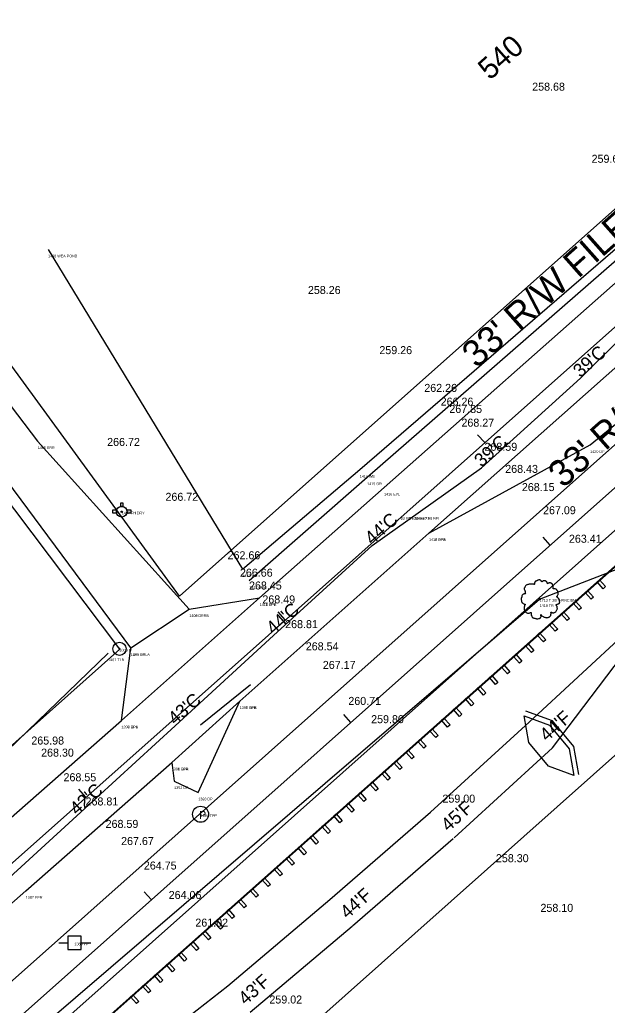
# Model space of a CAD drawing. Extents: x 49683 to 58852, y 49525 to 54803.
# Drawn here: x 54911.8 to 55132.1, y 52731.5 to 53100.7 of the extents above; entities that cross this region are included whole.
import ezdxf

# ---------------------------------------------------------------- set-up
doc = ezdxf.new("R2010")
doc.units = 0
for name, color, linetype in [('Level 1', 7, 'Continuous'), ('Level 10', 7, 'Continuous'), ('Level 11', 7, 'Continuous'), ('Level 12', 7, 'Continuous'), ('Level 13', 7, 'Continuous'), ('Level 18', 7, 'Continuous'), ('Level 19', 7, 'Continuous'), ('Level 20', 7, 'Continuous'), ('Level 21', 7, 'Continuous'), ('Level 25', 7, 'Continuous'), ('Level 27', 7, 'Continuous'), ('Level 3', 7, 'Continuous'), ('Level 32', 7, 'Continuous'), ('Level 33', 7, 'Continuous'), ('Level 34', 7, 'Continuous'), ('Level 48', 7, 'Continuous'), ('Level 51', 7, 'Continuous'), ('Level 53', 7, 'Continuous'), ('Level 57', 7, 'Continuous'), ('Level 58', 7, 'Continuous'), ('Level 59', 7, 'Continuous'), ('Level 60', 7, 'Continuous'), ('Level 61', 7, 'Continuous'), ('Level 62', 7, 'Continuous'), ('Level 7', 7, 'Continuous'), ('Level 8', 7, 'Continuous'), ('Level 9', 7, 'Continuous')]:
    doc.layers.add(name, color=color, linetype=linetype)

# ---------------------------------------------------------------- blocks, each defined once
blk = doc.blocks.new('PP')
at = {"layer": 'Level 9'}
for p, q in [((2.53, 2.45), (-2.47, 2.45)), ((-2.47, 2.45), (-2.47, -2.55)), ((2.53, -2.55), (2.53, 2.45)), ((-5.91, -0.11), (-2.44, -0.11)), ((-2.47, -2.55), (2.53, -2.55)), ((2.45, -0.11), (6.09, -0.11))]:
    blk.add_line(p, q, dxfattribs=at)
blk = doc.blocks.new('TPP')
at = {"layer": 'Level 9'}
blk.add_circle((0, 0), 3, dxfattribs=at)
blk.add_text('P', height=3, dxfattribs=at).set_placement((-0.59, -1.73))
blk = doc.blocks.new('FH')
at = {"layer": 'Level 9'}
for p, q in [((-1.92, 0.57), (-3.47, 0.57)), ((-3.47, 0.57), (-3.47, -0.43)), ((-0.46, 3.22), (-0.46, 1.95)), ((0.54, 3.22), (-0.46, 3.22)), ((0.54, 1.92), (0.54, 3.22)), ((3.53, 0.57), (1.92, 0.57)), ((3.53, -0.43), (3.53, 0.57)), ((-3.47, -0.43), (-1.95, -0.43)), ((1.95, -0.43), (3.53, -0.43))]:
    blk.add_line(p, q, dxfattribs=at)
for radius in [2, 0.25]:
    blk.add_circle((0, 0), radius, dxfattribs=at)
for start, end in [(163.3387, 192.315), (74.2455, 103.2128), (347.685, 16.6613)]:
    blk.add_arc((0, 0), 2, start, end, dxfattribs=at)
blk = doc.blocks.new('T1')
at = {"layer": 'Level 11'}
for centre, radius in [((0, 0), 0.25), ((-0.01, -0.02), 0.0001)]:
    blk.add_circle(centre, radius, dxfattribs=at)
for points in [[(0.13, 7.17), (-0.17, 7.19), (-0.49, 7.09), (-0.74, 6.99), (-0.97, 6.92), (-1.19, 6.82), (-1.49, 6.64), (-1.72, 6.44), (-1.84, 6.19), (-1.89, 5.97), (-1.94, 5.69), (-1.94, 5.52), (-2.07, 5.49), (-2.22, 5.52), (-2.47, 5.59), (-2.72, 5.59), (-2.97, 5.59), (-3.32, 5.57), (-3.67, 5.57), (-3.94, 5.52), (-4.27, 5.47), (-4.64, 5.34), (-4.99, 5.22), (-5.29, 4.97), (-5.54, 4.49), (-5.67, 4.14), (-5.82, 3.89), (-5.67, 3.44), (-5.49, 3.09), (-5.47, 2.89), (-5.39, 2.47), (-5.29, 2.24), (-5.17, 2.04), (-5.24, 2.02), (-5.62, 1.97), (-5.92, 1.87), (-6.34, 1.64), (-6.57, 1.42), (-6.67, 1.09), (-6.69, 0.75), (-6.79, 0.55), (-6.87, 0.27), (-6.89, 0.2), (-6.94, -0.13), (-6.84, -0.58), (-6.82, -0.93), (-6.69, -1.15), (-6.54, -1.33), (-6.37, -1.58), (-5.97, -1.8), (-5.64, -1.9), (-5.44, -1.93), (-5.62, -2.43), (-5.67, -2.78), (-5.79, -3.18), (-5.79, -3.25), (-5.84, -3.73), (-5.69, -4.05), (-5.62, -4.43), (-5.44, -4.65), (-5.17, -4.95), (-4.84, -5.18), (-4.34, -5.3), (-3.94, -5.28), (-3.37, -5.1), (-3.12, -5.03), (-3.14, -5.2), (-3.12, -5.58), (-3.12, -6), (-2.97, -6.33), (-2.87, -6.6), (-2.72, -6.85), (-2.39, -7.08), (-1.99, -7.15), (-1.57, -7.3), (-1.12, -7.38), (-0.62, -7.4), (-0.02, -7.25), (0.26, -7.13), (0.36, -6.95), (0.56, -6.58), (0.51, -6.35), (0.53, -5.75), (0.63, -5.93), (0.81, -6.28), (1.31, -6.58), (1.71, -6.75), (2.18, -6.9), (2.48, -6.98), (2.96, -6.9), (3.33, -6.83), (3.71, -6.7), (4.01, -6.43), (4.18, -6.15), (4.23, -5.88), (4.31, -5.5), (4.36, -5.33)], [(4.36, -5.33), (4.28, -5.15), (4.23, -4.9), (4.31, -4.93), (4.48, -4.98), (4.75, -5.1), (4.98, -5.18), (5.3, -5.15), (5.58, -5.05), (6.03, -4.78), (6.3, -4.3), (6.58, -3.9), (6.65, -3.58), (6.6, -3.35), (6.58, -2.85), (6.38, -2.6), (6.33, -2.48), (6.23, -2.08), (6.3, -2.03), (6.58, -1.98), (6.95, -1.85), (7.23, -1.73), (7.45, -1.55), (7.53, -1.33), (7.5, -0.93), (7.55, -0.53), (7.48, -0.38), (7.38, -0.23), (7.3, -0.03), (7.15, 0.12), (7.05, 0.27), (6.95, 0.37), (6.83, 0.52), (6.65, 0.65), (6.5, 0.7), (6.45, 0.85), (6.6, 1.04), (6.65, 1.14), (6.68, 1.37), (6.9, 1.72), (6.95, 2.12), (6.9, 2.54), (6.85, 2.82), (6.7, 3.09), (6.5, 3.34), (6.38, 3.52), (6.2, 3.64), (5.88, 3.77), (5.63, 3.82), (5.28, 3.82), (5.08, 3.87), (5.1, 3.92), (5.1, 4.07), (5.1, 4.34), (5.03, 4.79), (4.88, 5.29), (4.88, 5.32), (4.78, 5.57), (4.56, 5.77), (4.38, 5.87), (4.18, 5.99), (3.93, 6.02), (3.63, 6.02), (3.36, 5.97), (3.16, 5.87), (2.98, 5.74), (2.91, 5.89), (2.81, 6.19), (2.76, 6.34), (2.61, 6.52), (2.38, 6.72), (1.93, 6.84), (1.31, 6.77), (1.01, 6.57), (0.86, 6.39), (0.81, 6.52), (0.61, 6.72), (0.51, 6.89), (0.33, 7.02), (0.18, 7.12), (0.08, 7.17)]]:
    blk.add_spline(points, degree=3, dxfattribs=at)
blk = doc.blocks.new('IP')
at = {"layer": 'Level 12'}
for radius in [2.5, 0.25]:
    blk.add_circle((0, 0), radius, dxfattribs=at)

msp = doc.modelspace()

# ---------------------------------------------------------------- linework, layer by layer
at = {"layer": 'Level 1'}
for p, q in [((52544.81, 50683.3), (55534.58, 53340.86)), ((55086.14, 52942.25), (55083.48, 52945.23)), ((55011.4, 52875.81), (55008.74, 52878.8)), ((54936.65, 52809.37), (54934, 52812.36))]:
    msp.add_line(p, q, dxfattribs=at)
at = {"layer": 'Level 10'}
for p, q in [((55039.31, 52932.12), (55223.63, 53091.32)), ((54922.47, 53014.66), (54995.29, 52894.87)), ((54995.29, 52894.87), (55039.31, 52932.12))]:
    msp.add_line(p, q, dxfattribs=at)
at = {"layer": 'Level 11'}
for p, q in [((55106.73, 52883.65), (55187.95, 52915.03)), ((54913.43, 52717.81), (55106.73, 52883.65)), ((54711.21, 52637.72), (54944.99, 52863.38))]:
    msp.add_line(p, q, dxfattribs=at)
at = {"layer": 'Level 12'}
for p, q in [((54949.37, 52864.83), (54608.23, 53316.46)), ((54971.79, 52884.76), (54817.75, 53095.57))]:
    msp.add_line(p, q, dxfattribs=at)
at = {"layer": 'Level 13'}
for p, q in [((54971.79, 52884.76), (55235.68, 53119.33)), ((55279.53, 53070), (53969.03, 51905.11)), ((54949.37, 52864.83), (53925.18, 51954.44))]:
    msp.add_line(p, q, dxfattribs=at)
at = {"layer": 'Level 18'}
for p, q in [((55122.01, 52966.38), (55157.54, 53001.67)), ((55084.95, 52932.81), (55122.01, 52966.38)), ((55043.92, 52903.71), (55084.95, 52932.81)), ((55006.97, 52870.02), (55043.92, 52903.71)), ((55102.79, 52837.48), (55139.49, 52871.45)), ((54970.15, 52836.18), (55006.97, 52870.02)), ((55111.62, 52827.94), (55142.56, 52868.88)), ((55065.87, 52803.76), (55102.79, 52837.48)), ((54933.3, 52802.37), (54970.15, 52836.18)), ((55074.64, 52794.16), (55111.56, 52827.88)), ((54896.29, 52768.76), (54933.3, 52802.37)), ((55028.03, 52771.07), (55065.87, 52803.76)), ((55036.53, 52761.23), (55074.37, 52793.92)), ((54989.87, 52738.74), (55028.03, 52771.07)), ((54998.27, 52728.82), (55036.43, 52761.15)), ((54950.34, 52707.95), (54989.87, 52738.74))]:
    msp.add_line(p, q, dxfattribs=at)
at = {"layer": 'Level 19'}
for p, q in [((54181.77, 52078.16), (56150.85, 53828.45)), ((55110.69, 52903.86), (55108.03, 52906.85)), ((55035.94, 52837.42), (55033.29, 52840.41)), ((54961.2, 52770.99), (54958.55, 52773.98))]:
    msp.add_line(p, q, dxfattribs=at)
at = {"layer": 'Level 20'}
for p, q in [((54173.8, 52087.13), (55269.45, 53061.04)), ((54189.74, 52069.19), (55278.86, 53037.3))]:
    msp.add_line(p, q, dxfattribs=at)
at = {"layer": 'Level 27'}
for p, q in [((54196.38, 52061.72), (55282.79, 53027.4)), ((54196.55, 52061.53), (55282.95, 53027.22)), ((55128.29, 52890.07), (55129.17, 52890.86)), ((55130.55, 52887.53), (55128.29, 52890.07)), ((55129.17, 52890.86), (55131.43, 52888.32)), ((55123.81, 52886.09), (55124.69, 52886.87)), ((55126.07, 52883.55), (55123.81, 52886.09)), ((55124.69, 52886.87), (55126.95, 52884.33)), ((55131.43, 52888.32), (55130.55, 52887.53)), ((55119.32, 52882.1), (55120.21, 52882.89)), ((55121.58, 52879.56), (55119.32, 52882.1)), ((55120.21, 52882.89), (55122.46, 52880.35)), ((55126.95, 52884.33), (55126.07, 52883.55)), ((55114.84, 52878.12), (55115.72, 52878.9)), ((55117.1, 52875.57), (55114.84, 52878.12)), ((55115.72, 52878.9), (55117.98, 52876.36)), ((55122.46, 52880.35), (55121.58, 52879.56)), ((55110.35, 52874.13), (55111.24, 52874.91)), ((55111.24, 52874.91), (55113.5, 52872.37)), ((55117.98, 52876.36), (55117.1, 52875.57)), ((55105.87, 52870.14), (55106.75, 52870.93)), ((55106.75, 52870.93), (55109.01, 52868.39)), ((55112.61, 52871.59), (55110.35, 52874.13)), ((55113.5, 52872.37), (55112.61, 52871.59)), ((55101.38, 52866.16), (55102.27, 52866.94)), ((55102.27, 52866.94), (55104.53, 52864.4)), ((55108.13, 52867.6), (55105.87, 52870.14)), ((55109.01, 52868.39), (55108.13, 52867.6)), ((55103.64, 52863.62), (55101.38, 52866.16)), ((55104.53, 52864.4), (55103.64, 52863.62)), ((55096.9, 52862.17), (55097.78, 52862.96)), ((55099.16, 52859.63), (55096.9, 52862.17)), ((55097.78, 52862.96), (55100.04, 52860.41)), ((55100.04, 52860.41), (55099.16, 52859.63)), ((55092.42, 52858.18), (55093.3, 52858.97)), ((55094.67, 52855.64), (55092.42, 52858.18)), ((55093.3, 52858.97), (55095.56, 52856.43)), ((55095.56, 52856.43), (55094.67, 52855.64)), ((55087.93, 52854.2), (55088.81, 52854.98)), ((55090.19, 52851.66), (55087.93, 52854.2)), ((55088.81, 52854.98), (55091.07, 52852.44)), ((55091.07, 52852.44), (55090.19, 52851.66)), ((55083.45, 52850.21), (55084.33, 52851)), ((55085.7, 52847.67), (55083.45, 52850.21)), ((55084.33, 52851), (55086.59, 52848.46)), ((55086.59, 52848.46), (55085.7, 52847.67)), ((55078.96, 52846.23), (55079.85, 52847.01)), ((55081.22, 52843.68), (55078.96, 52846.23)), ((55079.85, 52847.01), (55082.1, 52844.47)), ((55074.48, 52842.24), (55075.36, 52843.03)), ((55076.74, 52839.7), (55074.48, 52842.24)), ((55075.36, 52843.03), (55077.62, 52840.48)), ((55082.1, 52844.47), (55081.22, 52843.68)), ((55069.99, 52838.25), (55070.88, 52839.04)), ((55072.25, 52835.71), (55069.99, 52838.25)), ((55070.88, 52839.04), (55073.14, 52836.5)), ((55077.62, 52840.48), (55076.74, 52839.7)), ((55065.51, 52834.27), (55066.39, 52835.05)), ((55067.77, 52831.73), (55065.51, 52834.27)), ((55066.39, 52835.05), (55068.65, 52832.51)), ((55073.14, 52836.5), (55072.25, 52835.71)), ((55061.02, 52830.28), (55061.91, 52831.07)), ((55063.28, 52827.74), (55061.02, 52830.28)), ((55061.91, 52831.07), (55064.17, 52828.53)), ((55068.65, 52832.51), (55067.77, 52831.73)), ((55056.54, 52826.3), (55057.42, 52827.08)), ((55058.8, 52823.75), (55056.54, 52826.3)), ((55057.42, 52827.08), (55059.68, 52824.54)), ((55064.17, 52828.53), (55063.28, 52827.74)), ((55052.06, 52822.31), (55052.94, 52823.09)), ((55052.94, 52823.09), (55055.2, 52820.55)), ((55059.68, 52824.54), (55058.8, 52823.75)), ((55047.57, 52818.32), (55048.45, 52819.11)), ((55048.45, 52819.11), (55050.71, 52816.57)), ((55054.31, 52819.77), (55052.06, 52822.31)), ((55055.2, 52820.55), (55054.31, 52819.77)), ((55043.09, 52814.34), (55043.97, 52815.12)), ((55043.97, 52815.12), (55046.23, 52812.58)), ((55049.83, 52815.78), (55047.57, 52818.32)), ((55050.71, 52816.57), (55049.83, 52815.78)), ((55045.34, 52811.8), (55043.09, 52814.34)), ((55046.23, 52812.58), (55045.34, 52811.8)), ((55038.6, 52810.35), (55039.49, 52811.14)), ((55040.86, 52807.81), (55038.6, 52810.35)), ((55039.49, 52811.14), (55041.74, 52808.59)), ((55041.74, 52808.59), (55040.86, 52807.81)), ((55034.12, 52806.36), (55035, 52807.15)), ((55036.38, 52803.82), (55034.12, 52806.36)), ((55035, 52807.15), (55037.26, 52804.61)), ((55037.26, 52804.61), (55036.38, 52803.82)), ((55029.63, 52802.38), (55030.52, 52803.16)), ((55031.89, 52799.84), (55029.63, 52802.38)), ((55030.52, 52803.16), (55032.77, 52800.62)), ((55032.77, 52800.62), (55031.89, 52799.84)), ((55025.15, 52798.39), (55026.03, 52799.18)), ((55027.41, 52795.85), (55025.15, 52798.39)), ((55026.03, 52799.18), (55028.29, 52796.64)), ((55028.29, 52796.64), (55027.41, 52795.85)), ((55020.66, 52794.41), (55021.55, 52795.19)), ((55022.92, 52791.86), (55020.66, 52794.41)), ((55021.55, 52795.19), (55023.81, 52792.65)), ((55016.18, 52790.42), (55017.06, 52791.2)), ((55018.44, 52787.88), (55016.18, 52790.42)), ((55017.06, 52791.2), (55019.32, 52788.66)), ((55023.81, 52792.65), (55022.92, 52791.86)), ((55011.7, 52786.43), (55012.58, 52787.22)), ((55013.95, 52783.89), (55011.7, 52786.43)), ((55012.58, 52787.22), (55014.84, 52784.68)), ((55019.32, 52788.66), (55018.44, 52787.88)), ((55007.21, 52782.45), (55008.09, 52783.23)), ((55009.47, 52779.91), (55007.21, 52782.45)), ((55008.09, 52783.23), (55010.35, 52780.69)), ((55014.84, 52784.68), (55013.95, 52783.89)), ((55002.73, 52778.46), (55003.61, 52779.25)), ((55004.98, 52775.92), (55002.73, 52778.46)), ((55003.61, 52779.25), (55005.87, 52776.7)), ((55010.35, 52780.69), (55009.47, 52779.91)), ((54998.24, 52774.48), (54999.13, 52775.26)), ((55000.5, 52771.93), (54998.24, 52774.48)), ((54999.13, 52775.26), (55001.38, 52772.72)), ((55005.87, 52776.7), (55004.98, 52775.92)), ((54993.76, 52770.49), (54994.64, 52771.27)), ((54994.64, 52771.27), (54996.9, 52768.73)), ((55001.38, 52772.72), (55000.5, 52771.93)), ((54989.27, 52766.5), (54990.16, 52767.29)), ((54990.16, 52767.29), (54992.41, 52764.75)), ((54996.02, 52767.95), (54993.76, 52770.49)), ((54996.9, 52768.73), (54996.02, 52767.95)), ((54991.53, 52763.96), (54989.27, 52766.5)), ((54992.41, 52764.75), (54991.53, 52763.96)), ((54984.79, 52762.52), (54985.67, 52763.3)), ((54987.05, 52759.97), (54984.79, 52762.52)), ((54985.67, 52763.3), (54987.93, 52760.76)), ((54987.93, 52760.76), (54987.05, 52759.97)), ((54980.3, 52758.53), (54981.19, 52759.32)), ((54982.56, 52755.99), (54980.3, 52758.53)), ((54981.19, 52759.32), (54983.45, 52756.77)), ((54983.45, 52756.77), (54982.56, 52755.99)), ((54975.82, 52754.54), (54976.7, 52755.33)), ((54978.08, 52752), (54975.82, 52754.54)), ((54976.7, 52755.33), (54978.96, 52752.79)), ((54978.96, 52752.79), (54978.08, 52752)), ((54971.33, 52750.56), (54972.22, 52751.34)), ((54973.59, 52748.02), (54971.33, 52750.56)), ((54972.22, 52751.34), (54974.48, 52748.8)), ((54974.48, 52748.8), (54973.59, 52748.02)), ((54966.85, 52746.57), (54967.73, 52747.36)), ((54969.11, 52744.03), (54966.85, 52746.57)), ((54967.73, 52747.36), (54969.99, 52744.82)), ((54962.37, 52742.59), (54963.25, 52743.37)), ((54964.62, 52740.04), (54962.37, 52742.59)), ((54963.25, 52743.37), (54965.51, 52740.83)), ((54969.99, 52744.82), (54969.11, 52744.03)), ((54957.88, 52738.6), (54958.76, 52739.38)), ((54960.14, 52736.06), (54957.88, 52738.6)), ((54958.76, 52739.38), (54961.02, 52736.84)), ((54965.51, 52740.83), (54964.62, 52740.04)), ((54953.4, 52734.61), (54954.28, 52735.4)), ((54955.66, 52732.07), (54953.4, 52734.61)), ((54954.28, 52735.4), (54956.54, 52732.86)), ((54961.02, 52736.84), (54960.14, 52736.06)), ((54956.54, 52732.86), (54955.66, 52732.07))]:
    msp.add_line(p, q, dxfattribs=at)
at = {"layer": 'Level 3'}
for p, q in [((55048.41, 52925.43), (55227.38, 53083.78)), ((55065.24, 52908.36), (55241.71, 53064.82)), ((54855.23, 53025.4), (54918.56, 52942.82)), ((54918.56, 52942.82), (54975.4, 52879.91)), ((54953.51, 52865.35), (54904.33, 52931.37)), ((55001.77, 52884.07), (55048.41, 52925.43)), ((54994.31, 52845.45), (55065.24, 52908.36)), ((54949.96, 52838.18), (55001.77, 52884.07)), ((54968.8, 52822.44), (54994.31, 52845.45)), ((54897.27, 52791.82), (54949.96, 52838.18)), ((54914.07, 52774.35), (54968.8, 52822.44)), ((54733.4, 52613.92), (54914.07, 52774.35))]:
    msp.add_line(p, q, dxfattribs=at)
at = {"layer": 'Level 33'}
msp.add_line((54231.59, 52022.1), (55608.96, 53246.42), dxfattribs=at)
at = {"layer": 'Level 34'}
for p, q in [((54979.65, 52836.56), (54998.37, 52851.58)), ((55111.54, 52838), (55101.54, 52841.64)), ((55102.66, 52829.9), (55100.9, 52839.88)), ((55100.9, 52839.88), (55110.42, 52836.41)), ((55119.62, 52828.37), (55111.54, 52838)), ((55110.42, 52836.41), (55117.86, 52827.55)), ((55110.09, 52821.04), (55102.66, 52829.9)), ((55117.86, 52827.55), (55119.62, 52817.57)), ((55121.47, 52817.9), (55119.62, 52828.37)), ((55119.62, 52817.57), (55110.09, 52821.04))]:
    msp.add_line(p, q, dxfattribs=at)
at = {"layer": 'Level 7'}
for p, q in [((55042.06, 52929.32), (55225.18, 53088.89)), ((54997.91, 52890.55), (55042.06, 52929.32))]:
    msp.add_line(p, q, dxfattribs=at)
at = {"layer": 'Level 8'}
for p, q in [((55125.68, 52941.41), (55179.24, 52985.05)), ((55065.24, 52908.36), (55125.68, 52941.41)), ((54975.4, 52879.91), (55001.77, 52884.07)), ((54953.51, 52865.35), (54975.4, 52879.91)), ((54949.96, 52838.18), (54953.51, 52865.35)), ((54978.78, 52811.23), (54994.31, 52845.45)), ((54968.8, 52822.44), (54969.71, 52815.44)), ((54969.71, 52815.44), (54978.78, 52811.23))]:
    msp.add_line(p, q, dxfattribs=at)

# ---------------------------------------------------------------- block references
at = {"layer": 'Level 11'}
msp.add_blockref('T1', (55106.73, 52883.65), dxfattribs=at)
at = {"layer": 'Level 12'}
msp.add_blockref('IP', (54949.25, 52864.99), dxfattribs=at)
at = {"layer": 'Level 9'}
for name, p in [('FH', (54950.06, 52916.37)), ('TPP', (54979.64, 52803.01)), ('PP', (54932.35, 52754.96))]:
    msp.add_blockref(name, p, dxfattribs=at)

# ---------------------------------------------------------------- texts
at = {"layer": 'Level 21'}
msp.add_text('540', height=8, rotation=41.6333, dxfattribs=at).set_placement((55088.08, 53077.77))
at = {"layer": 'Level 25'}
for p in [(55083.2, 52969.74), (55115.53, 52924.89)]:
    msp.add_text("33' R/W FILE # 408-B", height=10, rotation=41.6333, dxfattribs=at).set_placement(p)
at = {"layer": 'Level 32'}
for s, p in [('258.68', (55103.95, 53074.1)), ('259.68', (55126.21, 53047.09)), ('258.26', (55019.87, 52997.92)), ('259.26', (55046.66, 52975.4)), ('262.26', (55063.5, 52961.25)), ('266.26', (55069.63, 52956.1)), ('267.85', (55072.88, 52953.36)), ('268.27', (55077.43, 52948.23)), ('266.72', (54944.62, 52941)), ('268.59', (55086.06, 52939.19)), ('268.43', (55093.84, 52930.9)), ('268.15', (55100.08, 52924.09)), ('266.72', (54966.47, 52920.45)), ('267.09', (55108.02, 52915.42)), ('263.41', (55117.72, 52904.74)), ('262.66', (54989.76, 52898.55)), ('266.66', (54994.39, 52892.02)), ('268.45', (54997.79, 52887.22)), ('268.49', (55002.8, 52882.01)), ('268.81', (55011.34, 52872.74)), ('268.54', (55019.07, 52864.44)), ('267.17', (55025.47, 52857.46)), ('260.71', (55035.03, 52843.98)), ('259.80', (55043.58, 52837.14)), ('265.98', (54916.19, 52829.14)), ('268.30', (54919.86, 52824.61)), ('268.55', (54928.26, 52815.39)), ('268.81', (54936.52, 52806.32)), ('259.00', (55070.31, 52807.38)), ('268.59', (54944.04, 52797.91)), ('267.67', (54949.84, 52791.49)), ('258.30', (55090.35, 52785.06)), ('264.75', (54958.38, 52782.31)), ('264.06', (54967.68, 52771.29)), ('258.10', (55107.05, 52766.46)), ('261.02', (54977.67, 52760.92)), ('259.02', (55005.43, 52732.12))]:
    msp.add_text(s, height=3, dxfattribs=at).set_placement(p)
at = {"layer": 'Level 48'}
for s, p in [("39'C", (55122.01, 52966.38)), ("39'C", (55084.95, 52932.81)), ("44'C", (55043.92, 52903.71)), ("44'C", (55006.97, 52870.02)), ("43'C", (54970.15, 52836.18)), ("44'F", (55109.44, 52830.01)), ("42'C", (54933.3, 52802.37)), ("45'F", (55072.51, 52796.28)), ("44'F", (55034.68, 52763.59)), ("43'F", (54996.51, 52731.27))]:
    msp.add_text(s, height=5, rotation=41.6334, dxfattribs=at).set_placement(p)
at = {"layer": 'Level 51'}
for s in ['32 PT 538+66.21', '13 POT 538+57.98 REL']:
    msp.add_text(s, height=1, dxfattribs=at).set_placement((55054.73, 52913.33))
at = {"layer": 'Level 53'}
for s, p in [('1405 ERR', (54918.56, 52939.82)), ('1416 EPL', (55048.41, 52922.43)), ('1417 EPR', (55065.24, 52905.36)), ('1411 EPL', (55001.77, 52881.07)), ('1408 ERRB', (54975.4, 52876.91)), ('1400 ERLA', (54953.51, 52862.35)), ('1396 EPR', (54994.31, 52842.45)), ('1397 EPL', (54949.96, 52835.18)), ('1390 EPR', (54968.8, 52819.44)), ('1387 EPR', (54914.07, 52771.35))]:
    msp.add_text(s, height=1, dxfattribs=at).set_placement(p)
at = {"layer": 'Level 57'}
for s, p in [('1415 GR', (55042.06, 52926.32)), ('1412 GRA', (54997.91, 52887.55))]:
    msp.add_text(s, height=1, dxfattribs=at).set_placement(p)
at = {"layer": 'Level 58'}
for s, p in [('1420 DP', (55125.68, 52938.41)), ('1418 DPA', (55065.24, 52905.36)), ('1410 DPB', (55001.77, 52881.07)), ('1409 DP', (54975.4, 52876.91)), ('1399 DP', (54953.51, 52862.35)), ('1395 DPB', (54994.31, 52842.45)), ('1398 DPA', (54949.96, 52835.18)), ('1391 DPA', (54968.8, 52819.44)), ('1392 DP', (54969.71, 52812.44)), ('1393 DP', (54978.78, 52808.23))]:
    msp.add_text(s, height=1, dxfattribs=at).set_placement(p)
at = {"layer": 'Level 59'}
for s, p in [('1407 FH DRY', (54950.06, 52915.37)), ('1394 TPP', (54979.64, 52802.01)), ('1389 PP', (54932.35, 52753.96))]:
    msp.add_text(s, height=1, dxfattribs=at).set_placement(p)
at = {"layer": 'Level 60'}
for s, p in [('1406 WEA POND', (54922.47, 53011.66)), ('1414 WE ', (55039.31, 52929.12)), ('1413 WE ', (54995.29, 52891.87))]:
    msp.add_text(s, height=1, dxfattribs=at).set_placement(p)
at = {"layer": 'Level 61'}
for s, p in [('1713 T 30IN PINE BM 7', (55106.73, 52882.65)), ('1419 TR', (55106.73, 52880.65)), ('1401 TLB', (54944.99, 52860.38))]:
    msp.add_text(s, height=1, dxfattribs=at).set_placement(p)
at = {"layer": 'Level 62'}
msp.add_text('1009 IP', height=1, dxfattribs=at).set_placement((54949.25, 52863.99))

doc.saveas('drawing.dxf')
